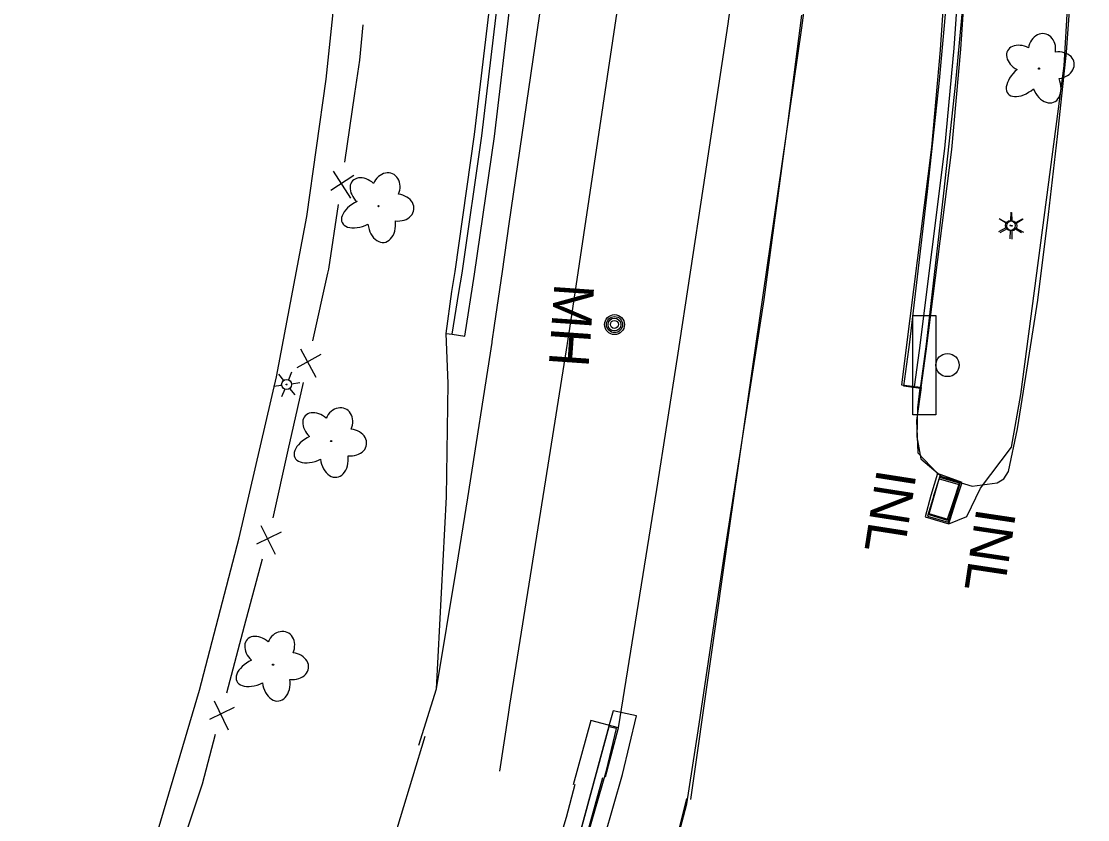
# Model space of a CAD drawing. Extents: x 588843 to 2552415, y 180129 to 269402.
# Drawn here: x 593439.1 to 593599.9, y 186049.3 to 186169.7 of the extents above; entities that cross this region are included whole.
import ezdxf

# ---------------------------------------------------------------- set-up
doc = ezdxf.new("R2010")
doc.units = 0
for name, color, linetype in [('Default', 7, 'Continuous'), ('E_DRN', 7, 'Continuous'), ('E_DRN_Text', 7, 'Continuous'), ('E_DWY', 7, 'Continuous'), ('E_FEN_P', 7, 'Continuous'), ('E_LAND_Vegetation', 7, 'Continuous'), ('E_LTG', 7, 'Continuous'), ('E_RDWY', 7, 'Continuous'), ('E_RDWY_AsphConc', 7, 'Continuous'), ('E_RDWY_C_and_G', 7, 'Continuous'), ('E_RDWY_PavtEdge', 7, 'Continuous'), ('E_RDWY_RumbleStrip', 7, 'Continuous'), ('E_SGN', 7, 'Continuous'), ('E_UTL_MH', 7, 'Continuous'), ('E_UTL_MH_Text', 7, 'Continuous')]:
    doc.layers.add(name, color=color, linetype=linetype)

# ---------------------------------------------------------------- blocks, each defined once
blk = doc.blocks.new('LPOL')
at = {"layer": 'Default'}
for p, q in [((-0.75, 1.3), (-2, 3.46)), ((0.75, 1.3), (2, 3.46)), ((-4, 0), (-1.5, 0)), ((1.5, 0), (4, 0)), ((-2, -3.46), (-0.75, -1.3)), ((2, -3.46), (0.75, -1.3))]:
    blk.add_line(p, q, dxfattribs=at)
for radius in [1.5, 1.5, 1.5, 0.125]:
    blk.add_circle((0, 0), radius, dxfattribs=at)
blk = doc.blocks.new('INLT_32')
at = {"layer": 'E_DRN_Text'}
blk.add_text('INL', height=12, dxfattribs=at).set_placement((-11.03, -6))
blk = doc.blocks.new('DTRE')
at = {"layer": 'Default'}
blk.add_circle((-0.18, 0), 0.183, dxfattribs=at)
for centre, major_axis, ratio in [((-1.87, 5.32), (1.36, -4.98), 0.782863), ((4.06, 2.74), (-5.27, -2.93), 0.691916), ((-5.87, 0.15), (4.93, -0.12), 0.832022), ((3.54, -3.71), (-5.01, 4.58), 0.560249), ((-2.49, -5.24), (1.8, 4.86), 0.716896)]:
    blk.add_ellipse(centre, major_axis=major_axis, ratio=ratio, start_param=1.570796, end_param=4.712389, dxfattribs=at)
blk = doc.blocks.new('MHO')
at = {"layer": 'Default'}
for centre, radius in [((0.08, -0.12), 3), ((0.08, -0.12), 2.43), ((0.07, -0.15), 1.94), ((0.02, -0.16), 1.21)]:
    blk.add_circle(centre, radius, dxfattribs=at)
blk = doc.blocks.new('MHT')
at = {"layer": 'E_UTL_MH_Text'}
blk.add_text('MH', height=12, dxfattribs=at).set_placement((-9.81, -6))
blk = doc.blocks.new('SGN_1')
at = {"layer": 'Default'}
blk.add_lwpolyline([(-3.5, -15), (-10.5, -15), (-10.5, 15), (-3.5, 15)], close=True, dxfattribs=at)
blk.add_circle((0, 0), 3.5, dxfattribs=at)
blk = doc.blocks.new('INLT_40_1')
at = {"layer": 'E_DRN_Text'}
blk.add_text('INL', height=39.37, dxfattribs=at).set_placement((-36.2, -19.7))
blk = doc.blocks.new('LPOL_4')
at = {"layer": 'E_LTG'}
for p, q in [((-2.5, 4.3), (-6.6, 11.4)), ((2.5, 4.3), (6.6, 11.4)), ((-13.1, 0), (-4.9, 0)), ((4.9, 0), (13.1, 0)), ((-6.6, -11.4), (-2.5, -4.3)), ((6.6, -11.4), (2.5, -4.3))]:
    blk.add_line(p, q, dxfattribs=at)
for radius in [4.92, 4.92, 4.92, 0.41]:
    blk.add_circle((0, 0), radius, dxfattribs=at)
blk = doc.blocks.new('DTRE_4')
at = {"layer": 'E_LAND_Vegetation'}
blk.add_circle((-0.6, 0), 0.601, dxfattribs=at)
for centre, major_axis, ratio in [((-6.1, 17.5), (4.5, -16.3), 0.782863), ((13.3, 9), (-17.3, -9.6), 0.691916), ((-19.3, 0.5), (16.2, -0.4), 0.832022), ((11.6, -12.2), (-16.4, 15), 0.560249), ((-8.2, -17.2), (5.9, 15.9), 0.716896)]:
    blk.add_ellipse(centre, major_axis=major_axis, ratio=ratio, start_param=1.570796, end_param=4.712389, dxfattribs=at)

msp = doc.modelspace()

# ---------------------------------------------------------------- linework, layer by layer
at = {"layer": 'E_DRN'}
for points in [[(593577.59, 186101.11), (593575.77, 186095.08), (593578.89, 186094.14), (593580.71, 186100.17)], [(593575.99, 186095.39), (593577.5, 186100.67), (593580.51, 186099.81), (593579, 186094.52), (593575.99, 186095.39)]]:
    msp.add_lwpolyline(points, close=True, dxfattribs=at)
at = {"layer": 'E_DWY'}
for points in [[(593422.26, 185952.34), (593434.65, 185981.09), (593447.89, 186013.5), (593456.97, 186038.4), (593465.97, 186068.8), (593471.95, 186091.79), (593477.61, 186116.08), (593482.16, 186140.28), (593485.09, 186160.99), (593487.03, 186179.67), (593488.46, 186197.05), (593489.49, 186217.32), (593489.86, 186241.29), (593489.93, 186244.63), (593490.42, 186245.94), (593491.41, 186246.66), (593492.53, 186247.06), (593494.68, 186247.33), (593497.02, 186247.11), (593504.49, 186245.06), (593510.18, 186242.66), (593511.98, 186241.33), (593513.62, 186240.04), (593514.79, 186237.91)], [(593574.69, 186114.32), (593572.21, 186114.66), (593573.11, 186121.29), (593575.75, 186144.05), (593577.55, 186160.78), (593579.16, 186178.59), (593580.43, 186197.52), (593581.44, 186215.28), (593582.06, 186230.86), (593582.24, 186244.32)], [(593574.69, 186114.32), (593575.59, 186120.98), (593578.24, 186143.77), (593580.04, 186160.53), (593581.66, 186178.39), (593582.93, 186197.37), (593583.93, 186215.16), (593584.56, 186230.8), (593584.73, 186243.61)], [(593574.59, 186114.34), (593574.24, 186111.42), (593574.13, 186107.04), (593574.74, 186103.68), (593578.04, 186100.95), (593582.47, 186099.6), (593586.27, 186100.08), (593587.24, 186100.67), (593587.99, 186101.79), (593589.3, 186108.25), (593590.57, 186116.1), (593592.38, 186127.65), (593594, 186140.56), (593595.37, 186152.33), (593596.7, 186165.07), (593597.86, 186181.1), (593598.58, 186193.81), (593599.26, 186206.66), (593599.11, 186218.96), (593599.44, 186235.57), (593599.48, 186239.78)]]:
    msp.add_lwpolyline(points, dxfattribs=at)
at = {"layer": 'E_FEN_P'}
for p, q in [((593489.27, 186146.45), (593485.79, 186144.2)), ((593486.15, 186147.08), (593488.76, 186143.02)), ((593484.3, 186119.43), (593480.67, 186117.43)), ((593481.24, 186120.28), (593483.54, 186116.04)), ((593475.26, 186093.63), (593477.39, 186089.3)), ((593478.28, 186092.65), (593474.58, 186090.81)), ((593471.23, 186066.2), (593467.52, 186064.36)), ((593468.21, 186067.18), (593470.33, 186062.85))]:
    msp.add_line(p, q, dxfattribs=at)
for points in [[(593490.6, 186169.17), (593490.12, 186163.83), (593489.37, 186158.8)], [(593489.37, 186158.8), (593487.84, 186148.46)], [(593486.89, 186142.06), (593485.45, 186132.34), (593485.31, 186131.73)], [(593485.31, 186131.73), (593483.02, 186121.53)], [(593481.61, 186115.22), (593479.32, 186105.02)], [(593479.32, 186105.02), (593477.03, 186094.82)], [(593475.42, 186088.56), (593472.73, 186078.46)], [(593472.73, 186078.46), (593470.04, 186068.36)], [(593468.37, 186062.11), (593466.38, 186054.64), (593465.52, 186052.06)], [(593465.52, 186052.06), (593462.23, 186042.13)]]:
    msp.add_lwpolyline(points, dxfattribs=at)
at = {"layer": 'E_RDWY'}
for points in [[(593486.2, 185883.3), (593489.18, 185893.96), (593493.89, 185911.07), (593499.24, 185928.93), (593507.1, 185955.12), (593509.61, 185962.65), (593517.48, 185983.79), (593527.72, 186012.54), (593531.1, 186022.16), (593535.59, 186036.96), (593539.47, 186051.68), (593541.2, 186062.67), (593545.15, 186089.33), (593548.03, 186107.77), (593551.11, 186127.76), (593554.74, 186154.6), (593556.82, 186170.65)], [(593460.64, 185955.04), (593467.37, 185970.47), (593472.37, 185982.97), (593477.68, 185995.79), (593482.62, 186008.82), (593487.75, 186022.71), (593492.35, 186036.69), (593496.3, 186049.62), (593500.01, 186061.89)], [(593491.32, 185955.6), (593497.06, 185969.3), (593501.79, 185980.97), (593506.3, 185991.99), (593509.96, 186002.19), (593515.39, 186017.82), (593519.12, 186029.28), (593522.69, 186040.75), (593525.65, 186051.45), (593526.79, 186055.65)], [(593522.56, 186054.59), (593521.25, 186049.62), (593517.22, 186036.16), (593512.49, 186021.93), (593508.45, 186009.64), (593504.16, 185997.05), (593500.25, 185987.06), (593494.6, 185972.85), (593489.15, 185959.57), (593487.18, 185955.06)], [(593506.3, 185953.15), (593509.39, 185962.62), (593513.59, 185974.38), (593520.05, 185991.23), (593526.18, 186009.1), (593530.36, 186021.24), (593534.44, 186034.67), (593538.07, 186046.79), (593539.46, 186052.49)]]:
    msp.add_lwpolyline(points, dxfattribs=at)
at = {"layer": 'E_RDWY_AsphConc'}
for points in [[(593578.99, 186093.91), (593581.67, 186094.99), (593583.73, 186099.27), (593588.43, 186105.47), (593589.84, 186113.39), (593596.37, 186162.99), (593599.33, 186214.01), (593599.91, 186223.8)], [(593499.08, 186060.49), (593501.71, 186069), (593503.23, 186097.96), (593503.5, 186115.08), (593503.2, 186122.63)], [(593574.8, 186114.46), (593574.08, 186109.49), (593574.3, 186104.6), (593577.27, 186101.49)]]:
    msp.add_lwpolyline(points, dxfattribs=at)
for points in [[(593577.27, 186101.49), (593576.27, 186098.16), (593575.42, 186094.98), (593578.99, 186093.91), (593579.94, 186096.97), (593581, 186100.15)], [(593577.55, 186100.89), (593576.64, 186098.14), (593575.94, 186095.3), (593578.7, 186094.43), (593579.63, 186097.14), (593580.58, 186100.01)]]:
    msp.add_lwpolyline(points, close=True, dxfattribs=at)
at = {"layer": 'E_RDWY_C_and_G'}
for points in [[(593574.8, 186114.46), (593573.81, 186114.59), (593571.89, 186114.8), (593572.59, 186120.49), (593576.39, 186150.74), (593576.39, 186150.74), (593577.73, 186165.42), (593577.73, 186165.42), (593580.34, 186204.21), (593580.34, 186204.21), (593581, 186214.2), (593581, 186214.2), (593581.1, 186215.77), (593581.1, 186215.77), (593581.58, 186223.61), (593581.58, 186223.61)], [(593503.2, 186122.63), (593504.03, 186128.94), (593504.52, 186131.98), (593507.46, 186152.64), (593509.9, 186173.37), (593509.9, 186173.37), (593512.17, 186198.28), (593513.73, 186223.24), (593513.73, 186223.24)], [(593503.2, 186122.63), (593504.1, 186122.51), (593506.01, 186122.23), (593507.46, 186131.56), (593510.47, 186152.35), (593512.95, 186173.21), (593512.95, 186173.21), (593515.21, 186197.99), (593516.72, 186222.83), (593516.72, 186222.83)], [(593504.1, 186122.51), (593505.11, 186128.79), (593505.6, 186131.7), (593508.57, 186152.45), (593511.02, 186173.27), (593511.02, 186173.27), (593513.25, 186198.11), (593514.72, 186223), (593514.72, 186223)], [(593573.81, 186114.59), (593574.55, 186120.05), (593578.39, 186150.51), (593578.39, 186150.51), (593579.78, 186165.64), (593579.78, 186165.64), (593582.42, 186204.42), (593582.42, 186204.42), (593583.06, 186214.09), (593583.06, 186214.09), (593583.15, 186215.66), (593583.15, 186215.66), (593583.54, 186223.47), (593583.54, 186223.47)], [(593574.8, 186114.46), (593575.55, 186119.97), (593579.4, 186150.38), (593579.4, 186150.38), (593580.78, 186165.49), (593580.78, 186165.49), (593583.4, 186204.19), (593583.4, 186204.19), (593584.05, 186213.96), (593584.05, 186213.96), (593584.14, 186215.56), (593584.14, 186215.56), (593584.51, 186223.45), (593584.51, 186223.45)]]:
    msp.add_lwpolyline(points, dxfattribs=at)
for points in [[(593528.35, 186065.69), (593527.87, 186063.92), (593508.9, 185993.97), (593506.55, 185985.32), (593508.77, 185990.93), (593513.58, 186004.11), (593520.59, 186025.03), (593525.7, 186041.92), (593529.75, 186056.08), (593531.89, 186064.93)], [(593527.69, 186063.27), (593514.63, 186015.11), (593518.21, 186025.79), (593523.3, 186042.62), (593527.33, 186056.71), (593528.85, 186063.02)]]:
    msp.add_lwpolyline(points, close=True, dxfattribs=at)
at = {"layer": 'E_RDWY_PavtEdge'}
for points in [[(593529.14, 186063.11), (593534.96, 186099.06), (593534.96, 186099.06), (593538.07, 186118.98), (593538.07, 186118.98), (593541.98, 186144.74), (593541.98, 186144.74), (593545.7, 186169.31), (593545.7, 186169.31), (593547.02, 186178.98), (593548.07, 186188.67), (593548.07, 186188.67), (593549.64, 186207.03), (593550.95, 186225.42), (593550.95, 186225.42)], [(593540.05, 186052.34), (593545.91, 186093.27), (593545.91, 186093.27), (593549.32, 186116.93), (593549.32, 186116.93), (593553.25, 186144.03), (593553.25, 186144.03), (593556.83, 186168.7), (593556.83, 186168.7), (593558.08, 186178.22), (593559.09, 186187.77), (593559.09, 186187.77), (593560.68, 186206.21), (593562.02, 186224.67), (593562.02, 186224.67)], [(593501.71, 186069), (593504.8, 186087.52), (593504.8, 186087.52), (593506.45, 186097.82), (593506.45, 186097.82), (593510.11, 186121.25), (593510.11, 186121.25), (593510.13, 186121.41), (593510.13, 186121.41), (593510.48, 186123.84), (593510.48, 186123.84), (593511.65, 186131.96), (593511.65, 186131.96), (593512.69, 186139.15), (593512.69, 186139.15), (593517.59, 186172.88), (593517.59, 186172.88), (593518.75, 186181.69), (593519.68, 186190.53), (593519.68, 186190.53), (593521.05, 186206.66), (593522.2, 186222.82), (593522.2, 186222.82)], [(593511.27, 186056.59), (593512.56, 186065.13), (593512.56, 186065.13), (593512.78, 186066.54), (593512.78, 186066.54), (593518.22, 186100.56), (593518.22, 186100.56), (593521.34, 186120.17), (593521.34, 186120.17), (593521.84, 186123.39), (593521.84, 186123.39), (593528.96, 186171.15), (593528.96, 186171.15), (593530.11, 186179.73), (593531, 186188.34), (593531, 186188.34), (593532.38, 186205.42), (593533.51, 186222.52), (593533.51, 186222.52)]]:
    msp.add_lwpolyline(points, dxfattribs=at)
at = {"layer": 'E_RDWY_RumbleStrip'}
for points in [[(593529.14, 186063.11), (593524.98, 186064.24), (593522.34, 186054.54)], [(593527.18, 186055.75), (593529.14, 186063.11)]]:
    msp.add_lwpolyline(points, dxfattribs=at)

# ---------------------------------------------------------------- block references
at = {"layer": 'E_DRN_Text'}
for name, p, xscale, yscale, rotation in [('INLT_40_1', (593570.28, 186096.41), 0.1524003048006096, 0.15240030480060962, -98.86795899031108), ('INLT_32', (593585.32, 186090.54), 0.5, 0.5, -98.54264241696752)]:
    msp.add_blockref(name, p, dxfattribs=dict(at, xscale=xscale, yscale=yscale, rotation=rotation))
at = {"layer": 'E_LAND_Vegetation'}
for name, p, xscale, yscale, rotation in [('DTRE_4', (593592.56, 186162.48), 0.1524003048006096, 0.1524003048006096, -97.36026881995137), ('DTRE', (593492.94, 186141.74), 0.49999999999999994, 0.5000000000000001, -112.01766453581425), ('DTRE', (593485.8, 186106.31), 0.49999999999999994, 0.5000000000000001, -112.01766453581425), ('DTRE', (593477.05, 186072.57), 0.49999999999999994, 0.5000000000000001, -112.01766453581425)]:
    msp.add_blockref(name, p, dxfattribs=dict(at, xscale=xscale, yscale=yscale, rotation=rotation))
at = {"layer": 'E_LTG'}
for name, p, xscale, yscale, rotation in [('LPOL', (593588.24, 186138.9), 0.4999999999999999, 0.4999999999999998, -151.83730204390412), ('LPOL_4', (593588.46, 186138.86), 0.1524003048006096, 0.1524003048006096, -89.2544447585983), ('LPOL', (593479.12, 186114.92), 0.49999999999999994, 0.5000000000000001, -112.01766453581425)]:
    msp.add_blockref(name, p, dxfattribs=dict(at, xscale=xscale, yscale=yscale, rotation=rotation))
at = {"layer": 'E_SGN', "xscale": 0.5, "yscale": 0.5}
msp.add_blockref('SGN_1', (593578.77, 186117.85), dxfattribs=at)
at = {"layer": 'E_UTL_MH', "xscale": 0.49999999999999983, "yscale": 0.4999999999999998, "rotation": -93.98106539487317}
msp.add_blockref('MHO', (593528.63, 186123.99), dxfattribs=at)
at = {"layer": 'E_UTL_MH_Text', "xscale": 0.49999999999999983, "yscale": 0.4999999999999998, "rotation": -93.98106539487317}
msp.add_blockref('MHT', (593522.17, 186125.17), dxfattribs=at)

doc.saveas('drawing.dxf')
